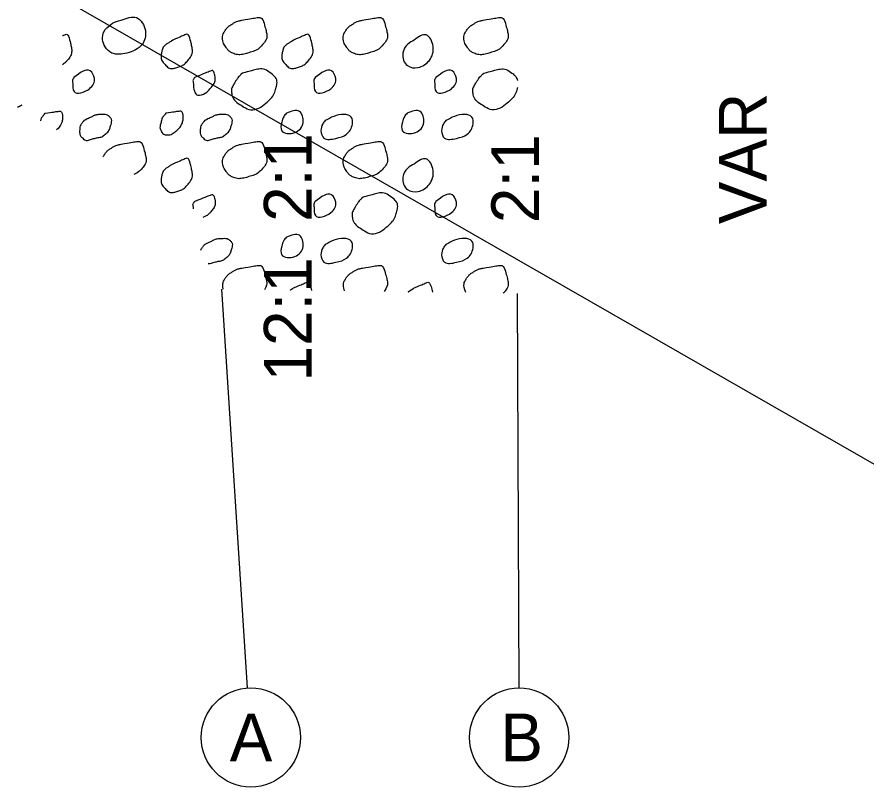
# Model space of a CAD drawing. Extents: x 0 to 2278, y -264 to 330.
# Drawn here: x 275.97 to 313.29, y 188.65 to 222.49 of the extents above; entities that cross this region are included whole.
import ezdxf

# ---------------------------------------------------------------- set-up
doc = ezdxf.new("R2010")
doc.units = 0
for name, color, linetype in [('DR_P_Culvert', 7, 'Continuous'), ('TX_X_10', 7, 'Continuous'), ('XS_P_Finished_Grade', 7, 'Continuous')]:
    doc.layers.add(name, color=color, linetype=linetype)

msp = doc.modelspace()

# ---------------------------------------------------------------- linework, layer by layer
at = {"layer": 'DR_P_Culvert'}
msp.add_line((275.975, 224.45), (325.671, 195.939), dxfattribs=at)
for centre in [(286.253, 190.831), (298.049, 190.831)]:
    msp.add_circle(centre, 2.179, dxfattribs=at)
at = {"layer": 'TX_X_10'}
for p, q in [((286.112, 193.006), (284.975, 210.53)), ((298.041, 193.01), (297.975, 210.34))]:
    msp.add_line(p, q, dxfattribs=at)
at = {"layer": 'XS_P_Finished_Grade'}
for points in [[(280.547, 222.343), (281.229, 222.457), (281.617, 221.887), (281.472, 221.277), (280.804, 220.898), (280.144, 220.902), (279.845, 221.17), (279.79, 221.837), (280.097, 222.157), (280.436, 222.32), (280.56, 222.346)], [(293.428, 221.47), (293.956, 221.696), (294.267, 221.188), (294.1, 220.581), (293.6, 220.262), (293.133, 220.351), (292.933, 220.89), (293.152, 221.291), (293.428, 221.47)], [(278.48, 219.827), (279.192, 220.116), (279.381, 219.788), (279.157, 219.335), (278.482, 219.208), (278.424, 219.568), (278.43, 219.75), (278.48, 219.827)], [(289.087, 219.827), (289.8, 220.116), (289.988, 219.788), (289.765, 219.335), (289.09, 219.208), (289.031, 219.568), (289.037, 219.75), (289.087, 219.827)], [(294.391, 219.827), (295.103, 220.116), (295.292, 219.788), (295.068, 219.335), (294.393, 219.208), (294.335, 219.568), (294.341, 219.75), (294.391, 219.827)], [(287.818, 218.257), (288.391, 218.34), (288.547, 217.848), (288.187, 217.407), (287.607, 217.492), (287.611, 217.86), (287.698, 218.105), (287.818, 218.257)], [(293.122, 218.257), (293.695, 218.34), (293.851, 217.848), (293.491, 217.407), (292.911, 217.492), (292.915, 217.86), (293.002, 218.105), (293.122, 218.257)], [(289.525, 217.932), (289.9, 218.119), (290.351, 218.205), (290.667, 218.084), (290.718, 217.779), (290.462, 217.334), (289.992, 217.154), (289.465, 217.163), (289.336, 217.487), (289.413, 217.787), (289.525, 217.932)], [(294.828, 217.932), (295.203, 218.119), (295.655, 218.205), (295.971, 218.084), (296.022, 217.779), (295.766, 217.334), (295.296, 217.154), (294.768, 217.163), (294.64, 217.487), (294.717, 217.787), (294.828, 217.932)], [(293.428, 216.024), (293.956, 216.25), (294.267, 215.743), (294.1, 215.135), (293.6, 214.817), (293.133, 214.905), (292.933, 215.444), (293.152, 215.845), (293.428, 216.024)], [(289.087, 214.382), (289.8, 214.67), (289.988, 214.343), (289.765, 213.889), (289.09, 213.763), (289.031, 214.123), (289.037, 214.304), (289.087, 214.382)], [(294.391, 214.382), (295.103, 214.67), (295.292, 214.343), (295.068, 213.889), (294.393, 213.763), (294.335, 214.123), (294.341, 214.304), (294.391, 214.382)], [(287.818, 212.811), (288.391, 212.895), (288.547, 212.402), (288.187, 211.961), (287.607, 212.046), (287.611, 212.415), (287.698, 212.66), (287.818, 212.811)], [(289.525, 212.486), (289.9, 212.673), (290.351, 212.76), (290.667, 212.638), (290.718, 212.333), (290.462, 211.888), (289.992, 211.708), (289.465, 211.717), (289.336, 212.041), (289.413, 212.341), (289.525, 212.486)], [(294.828, 212.486), (295.203, 212.673), (295.655, 212.76), (295.971, 212.638), (296.022, 212.333), (295.766, 211.888), (295.296, 211.708), (294.768, 211.717), (294.64, 212.041), (294.717, 212.341), (294.828, 212.486)]]:
    msp.add_spline(points, degree=3, dxfattribs=at)
for points, degree in [([(285.851, 222.343), (286.078, 222.382), (286.305, 222.426), (286.532, 222.457), (286.759, 222.489), (286.864, 222.1), (286.921, 221.887), (286.973, 221.694), (286.939, 221.458), (286.776, 221.277), (286.576, 221.056), (286.354, 220.971), (286.107, 220.898), (285.895, 220.836), (285.658, 220.813), (285.447, 220.902), (285.319, 220.956), (285.226, 221.049), (285.148, 221.17), (285.019, 221.371), (284.98, 221.648), (285.093, 221.837), (285.169, 221.963), (285.27, 222.074), (285.401, 222.157), (285.512, 222.228), (285.617, 222.294), (285.74, 222.32), (285.781, 222.328), (285.822, 222.337), (285.863, 222.346)], 3), ([(291.155, 222.343), (291.382, 222.382), (291.609, 222.426), (291.836, 222.457), (292.063, 222.489), (292.168, 222.1), (292.225, 221.887), (292.276, 221.694), (292.243, 221.458), (292.08, 221.277), (291.88, 221.056), (291.658, 220.971), (291.411, 220.898), (291.199, 220.836), (290.962, 220.813), (290.751, 220.902), (290.623, 220.956), (290.53, 221.049), (290.452, 221.17), (290.323, 221.371), (290.284, 221.648), (290.397, 221.837), (290.472, 221.963), (290.574, 222.074), (290.705, 222.157), (290.815, 222.228), (290.921, 222.294), (291.043, 222.32), (291.085, 222.328), (291.126, 222.337), (291.167, 222.346)], 3), ([(296.458, 222.343), (296.685, 222.382), (296.913, 222.426), (297.14, 222.457), (297.366, 222.489), (297.472, 222.1), (297.528, 221.887), (297.58, 221.694), (297.547, 221.458), (297.383, 221.277), (297.184, 221.056), (296.961, 220.971), (296.715, 220.898), (296.503, 220.836), (296.266, 220.813), (296.055, 220.902), (295.927, 220.956), (295.834, 221.049), (295.756, 221.17), (295.626, 221.371), (295.588, 221.648), (295.701, 221.837), (295.776, 221.963), (295.878, 222.074), (296.008, 222.157), (296.119, 222.228), (296.225, 222.294), (296.347, 222.32), (296.388, 222.328), (296.43, 222.337), (296.471, 222.346)], 3), ([(277.975, 221.666), (277.998, 221.676), (278.021, 221.686), (278.045, 221.696), (278.227, 221.774), (278.316, 221.374), (278.356, 221.188), (278.398, 220.992), (278.347, 220.772), (278.189, 220.581), (278.121, 220.5), (278.05, 220.439), (277.975, 220.39)], 3), ([(282.821, 221.47), (282.997, 221.545), (283.173, 221.621), (283.349, 221.696), (283.531, 221.774), (283.62, 221.374), (283.66, 221.188), (283.702, 220.992), (283.651, 220.772), (283.492, 220.581), (283.343, 220.402), (283.172, 220.317), (282.992, 220.262), (282.848, 220.219), (282.667, 220.212), (282.526, 220.351), (282.355, 220.52), (282.292, 220.718), (282.326, 220.89), (282.353, 221.026), (282.417, 221.206), (282.545, 221.291), (282.637, 221.352), (282.729, 221.41), (282.821, 221.47)], 3), ([(288.125, 221.47), (288.301, 221.545), (288.476, 221.621), (288.652, 221.696), (288.835, 221.774), (288.923, 221.374), (288.963, 221.188), (289.006, 220.992), (288.955, 220.772), (288.796, 220.581), (288.646, 220.402), (288.476, 220.317), (288.296, 220.262), (288.152, 220.219), (287.971, 220.212), (287.83, 220.351), (287.659, 220.52), (287.595, 220.718), (287.63, 220.89), (287.657, 221.026), (287.721, 221.206), (287.848, 221.291), (287.94, 221.352), (288.033, 221.41), (288.125, 221.47)], 3), ([(285.882, 220.016), (286.06, 220.063), (286.238, 220.11), (286.416, 220.156), (286.676, 220.223), (286.937, 220.176), (287.197, 219.958), (287.399, 219.79), (287.412, 219.541), (287.358, 219.355), (287.291, 219.12), (287.143, 218.897), (286.915, 218.702), (286.63, 218.459), (286.234, 218.363), (285.942, 218.536), (285.706, 218.676), (285.457, 218.886), (285.411, 219.133), (285.383, 219.288), (285.463, 219.467), (285.553, 219.611), (285.618, 219.714), (285.676, 219.817), (285.761, 219.9), (285.801, 219.939), (285.842, 219.977), (285.882, 220.016)], 3), ([(296.49, 220.016), (296.667, 220.063), (296.846, 220.11), (297.023, 220.156), (297.283, 220.223), (297.545, 220.176), (297.805, 219.958), (297.897, 219.881), (297.95, 219.787), (297.975, 219.689)], 3), ([(283.783, 219.827), (284.021, 219.923), (284.259, 220.026), (284.496, 220.116), (284.613, 220.16), (284.674, 219.9), (284.685, 219.788), (284.699, 219.639), (284.584, 219.483), (284.461, 219.335), (284.294, 219.134), (283.873, 218.987), (283.786, 219.208), (283.74, 219.326), (283.732, 219.447), (283.727, 219.568), (283.725, 219.629), (283.702, 219.696), (283.733, 219.75), (283.749, 219.777), (283.767, 219.801), (283.783, 219.827)], 3), ([(297.975, 219.389), (297.972, 219.378), (297.969, 219.366), (297.966, 219.355), (297.899, 219.12), (297.75, 218.897), (297.522, 218.702), (297.237, 218.459), (296.841, 218.363), (296.55, 218.536), (296.313, 218.676), (296.064, 218.886), (296.018, 219.133), (295.99, 219.288), (296.07, 219.467), (296.161, 219.611), (296.226, 219.714), (296.283, 219.817), (296.368, 219.9), (296.409, 219.939), (296.449, 219.977), (296.49, 220.016)], 3), ([(276.194, 218.617), (276.133, 218.577), (276.069, 218.543), (276.004, 218.517)], 2), ([(277.211, 218.257), (277.402, 218.284), (277.593, 218.314), (277.784, 218.34), (277.954, 218.363), (277.994, 217.995), (277.94, 217.848), (277.899, 217.736), (277.816, 217.624), (277.718, 217.527)], 3), ([(282.515, 218.257), (282.706, 218.284), (282.896, 218.314), (283.087, 218.34), (283.258, 218.363), (283.297, 217.995), (283.244, 217.848), (283.184, 217.685), (283.036, 217.523), (282.884, 217.407), (282.726, 217.286), (282.395, 217.306), (282.304, 217.492), (282.246, 217.608), (282.275, 217.743), (282.307, 217.86), (282.33, 217.943), (282.341, 218.037), (282.395, 218.105), (282.435, 218.156), (282.475, 218.206), (282.515, 218.257)], 3), ([(277.021, 217.93), (277.036, 217.992), (277.052, 218.056), (277.091, 218.105), (277.131, 218.156), (277.171, 218.206), (277.211, 218.257)], 3), ([(278.917, 217.932), (279.042, 217.994), (279.167, 218.057), (279.292, 218.119), (279.43, 218.187), (279.594, 218.201), (279.744, 218.205), (279.854, 218.208), (279.96, 218.183), (280.06, 218.084), (280.151, 217.994), (280.138, 217.874), (280.111, 217.779), (280.067, 217.622), (280.008, 217.461), (279.855, 217.334), (279.705, 217.209), (279.546, 217.192), (279.385, 217.154), (279.216, 217.115), (279.022, 217.015), (278.857, 217.163), (278.748, 217.261), (278.726, 217.375), (278.729, 217.487), (278.731, 217.586), (278.743, 217.703), (278.806, 217.787), (278.843, 217.836), (278.88, 217.883), (278.917, 217.932)], 3), ([(284.221, 217.932), (284.346, 217.994), (284.471, 218.057), (284.596, 218.119), (284.733, 218.187), (284.898, 218.201), (285.047, 218.205), (285.158, 218.208), (285.264, 218.183), (285.363, 218.084), (285.454, 217.994), (285.441, 217.874), (285.415, 217.779), (285.37, 217.622), (285.312, 217.461), (285.158, 217.334), (285.008, 217.209), (284.85, 217.192), (284.688, 217.154), (284.52, 217.115), (284.326, 217.015), (284.161, 217.163), (284.052, 217.261), (284.029, 217.375), (284.032, 217.487), (284.035, 217.586), (284.047, 217.703), (284.11, 217.787), (284.147, 217.836), (284.184, 217.883), (284.221, 217.932)], 3), ([(279.766, 216.345), (279.773, 216.361), (279.781, 216.377), (279.79, 216.392), (279.865, 216.517), (279.967, 216.628), (280.097, 216.712), (280.208, 216.782), (280.313, 216.848), (280.436, 216.874), (280.477, 216.883), (280.519, 216.892), (280.56, 216.9)], 3), ([(280.547, 216.898), (280.774, 216.937), (281.002, 216.98), (281.229, 217.012), (281.455, 217.043), (281.56, 216.654), (281.617, 216.442), (281.669, 216.248), (281.635, 216.012), (281.472, 215.832), (281.36, 215.708), (281.241, 215.626), (281.115, 215.566)], 3), ([(285.851, 216.898), (286.078, 216.937), (286.305, 216.98), (286.532, 217.012), (286.759, 217.043), (286.864, 216.654), (286.921, 216.442), (286.973, 216.248), (286.939, 216.012), (286.776, 215.832), (286.576, 215.61), (286.354, 215.525), (286.107, 215.453), (285.895, 215.39), (285.658, 215.368), (285.447, 215.457), (285.319, 215.511), (285.226, 215.604), (285.148, 215.724), (285.019, 215.925), (284.98, 216.202), (285.093, 216.392), (285.169, 216.517), (285.27, 216.628), (285.401, 216.712), (285.512, 216.782), (285.617, 216.848), (285.74, 216.874), (285.781, 216.883), (285.822, 216.892), (285.863, 216.9)], 3), ([(291.155, 216.898), (291.382, 216.937), (291.609, 216.98), (291.836, 217.012), (292.063, 217.043), (292.168, 216.654), (292.225, 216.442), (292.276, 216.248), (292.243, 216.012), (292.08, 215.832), (291.88, 215.61), (291.658, 215.525), (291.411, 215.453), (291.199, 215.39), (290.962, 215.368), (290.751, 215.457), (290.623, 215.511), (290.53, 215.604), (290.452, 215.724), (290.323, 215.925), (290.284, 216.202), (290.397, 216.392), (290.472, 216.517), (290.574, 216.628), (290.705, 216.712), (290.815, 216.782), (290.921, 216.848), (291.043, 216.874), (291.085, 216.883), (291.126, 216.892), (291.167, 216.9)], 3), ([(282.821, 216.024), (282.997, 216.099), (283.173, 216.175), (283.349, 216.25), (283.531, 216.328), (283.62, 215.928), (283.66, 215.743), (283.702, 215.546), (283.651, 215.326), (283.492, 215.135), (283.343, 214.956), (283.172, 214.871), (282.992, 214.817), (282.848, 214.773), (282.667, 214.766), (282.526, 214.905), (282.355, 215.074), (282.292, 215.272), (282.326, 215.444), (282.353, 215.581), (282.417, 215.76), (282.545, 215.845), (282.637, 215.906), (282.729, 215.964), (282.821, 216.024)], 3), ([(283.783, 214.382), (284.021, 214.478), (284.259, 214.58), (284.496, 214.67), (284.613, 214.715), (284.674, 214.454), (284.685, 214.343), (284.699, 214.193), (284.584, 214.037), (284.461, 213.889), (284.388, 213.801), (284.265, 213.723), (284.144, 213.682)], 3), ([(291.186, 214.57), (291.364, 214.618), (291.542, 214.664), (291.72, 214.71), (291.98, 214.778), (292.241, 214.73), (292.501, 214.513), (292.703, 214.344), (292.716, 214.095), (292.662, 213.909), (292.595, 213.674), (292.446, 213.451), (292.218, 213.257), (291.933, 213.013), (291.538, 212.918), (291.246, 213.09), (291.01, 213.23), (290.76, 213.44), (290.715, 213.688), (290.686, 213.842), (290.767, 214.022), (290.857, 214.165), (290.922, 214.268), (290.979, 214.372), (291.065, 214.454), (291.105, 214.493), (291.145, 214.532), (291.186, 214.57)], 3), ([(283.73, 214.056), (283.729, 214.078), (283.728, 214.1), (283.727, 214.123), (283.725, 214.183), (283.702, 214.25), (283.733, 214.304), (283.749, 214.331), (283.767, 214.356), (283.783, 214.382)], 3), ([(284.221, 212.486), (284.346, 212.549), (284.471, 212.611), (284.596, 212.673), (284.733, 212.742), (284.898, 212.755), (285.047, 212.76), (285.158, 212.763), (285.264, 212.737), (285.363, 212.638), (285.454, 212.548), (285.441, 212.428), (285.415, 212.333), (285.37, 212.176), (285.312, 212.016), (285.158, 211.888), (285.008, 211.764), (284.85, 211.746), (284.688, 211.708), (284.592, 211.686), (284.487, 211.643), (284.384, 211.639)], 3), ([(284.061, 212.244), (284.072, 212.279), (284.088, 212.312), (284.11, 212.341), (284.147, 212.39), (284.184, 212.438), (284.221, 212.486)], 3), ([(285.044, 210.529), (285.011, 210.676), (285.023, 210.828), (285.093, 210.946), (285.169, 211.071), (285.27, 211.183), (285.401, 211.266), (285.512, 211.336), (285.617, 211.402), (285.74, 211.428), (285.781, 211.437), (285.822, 211.446), (285.863, 211.455)], 3), ([(285.851, 211.452), (286.078, 211.491), (286.305, 211.534), (286.532, 211.566), (286.759, 211.597), (286.864, 211.209), (286.921, 210.996), (286.962, 210.842), (286.949, 210.661), (286.86, 210.503)], 3), ([(290.369, 210.451), (290.313, 210.62), (290.314, 210.806), (290.397, 210.946), (290.472, 211.071), (290.574, 211.183), (290.705, 211.266), (290.815, 211.336), (290.921, 211.402), (291.043, 211.428), (291.085, 211.437), (291.126, 211.446), (291.167, 211.455)], 3), ([(291.155, 211.452), (291.382, 211.491), (291.609, 211.534), (291.836, 211.566), (292.063, 211.597), (292.168, 211.209), (292.225, 210.996), (292.273, 210.817), (292.247, 210.6), (292.113, 210.426)], 3), ([(295.704, 210.373), (295.618, 210.56), (295.605, 210.785), (295.701, 210.946), (295.776, 211.071), (295.878, 211.183), (296.008, 211.266), (296.119, 211.336), (296.225, 211.402), (296.347, 211.428), (296.388, 211.437), (296.43, 211.446), (296.471, 211.455)], 3), ([(296.458, 211.452), (296.685, 211.491), (296.913, 211.534), (297.14, 211.566), (297.366, 211.597), (297.472, 211.209), (297.528, 210.996), (297.58, 210.802), (297.547, 210.566), (297.383, 210.386), (297.372, 210.373), (297.361, 210.361), (297.349, 210.349)], 3), ([(288.125, 210.578), (288.301, 210.654), (288.476, 210.729), (288.652, 210.805), (288.787, 210.862), (288.871, 210.658), (288.922, 210.473)], 3), ([(293.428, 210.578), (293.604, 210.654), (293.78, 210.729), (293.956, 210.805), (294.11, 210.871), (294.198, 210.594), (294.245, 210.395)], 3), ([(287.982, 210.486), (288.03, 210.517), (288.077, 210.547), (288.125, 210.578)], 2), ([(293.169, 210.411), (293.255, 210.468), (293.342, 210.522), (293.428, 210.578)], 2)]:
    msp.add_open_spline(points, degree=degree, dxfattribs=at)

# ---------------------------------------------------------------- texts
at = {"layer": 'DR_P_Culvert'}
for s, p in [('VAR', (308.925, 213.382)), ('2:1', (288.925, 213.481)), ('2:1', (298.925, 213.429)), ('12:1', (288.925, 206.466))]:
    msp.add_text(s, height=2.1, rotation=90, dxfattribs=at).set_placement(p)
for s, p in [('A', (285.325, 189.781)), ('B', (297.221, 189.781))]:
    msp.add_text(s, height=2.1, dxfattribs=at).set_placement(p)

doc.saveas('drawing.dxf')
